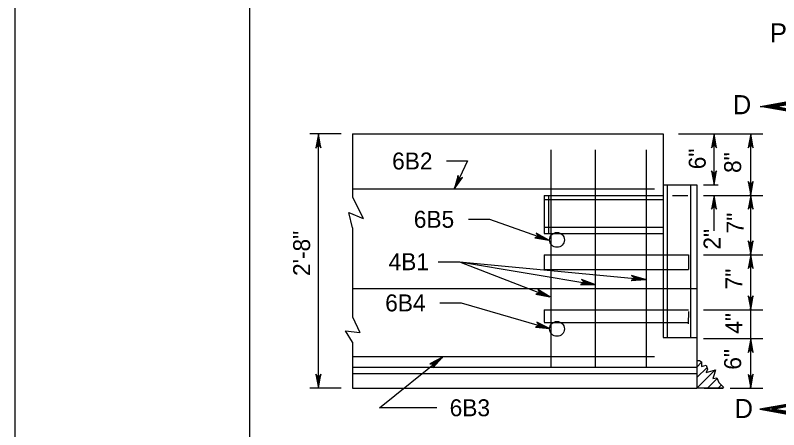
# Model space of a CAD drawing. Extents: x 499866 to 500993, y 499985 to 500645.
# Drawn here: x 499944.8 to 500124.8, y 500452.8 to 500550.5 of the extents above; entities that cross this region are included whole.
import ezdxf

# ---------------------------------------------------------------- set-up
doc = ezdxf.new("R2010")
doc.units = 0
for name, color, linetype in [('1', 7, 'Continuous'), ('24', 7, 'Continuous'), ('41', 7, 'Continuous'), ('5', 7, 'Continuous'), ('60', 7, 'Continuous')]:
    doc.layers.add(name, color=color, linetype=linetype)

msp = doc.modelspace()

# ---------------------------------------------------------------- linework, layer by layer
at = {"layer": '1'}
msp.add_line((500000, 500630), (500000, 500000), dxfattribs=at)
at = {"layer": '24'}
for points in [[(500109.52, 500522.52), (500108.95, 500519.24), (500109.52, 500520.03), (500110.09, 500519.26), (500109.52, 500522.52), (500109.53, 500522.3), (500108.99, 500519.34), (500109.53, 500520.09), (500110.05, 500519.39), (500109.54, 500522.18), (500109.52, 500522.07), (500109.07, 500519.53), (500109.53, 500520.1), (500109.98, 500519.52), (500109.52, 500522.02), (500109.54, 500521.92), (500109.14, 500519.7), (500109.52, 500520.13), (500109.92, 500519.69), (500109.54, 500521.6), (500109.54, 500521.41), (500109.22, 500519.86), (500109.51, 500520.16), (500109.84, 500519.84), (500109.52, 500521.38), (500109.51, 500521.21), (500109.31, 500520.04), (500109.54, 500520.26), (500109.76, 500520.02), (500109.52, 500521.05), (500109.51, 500520.88), (500109.37, 500520.18), (500109.53, 500520.29), (500109.71, 500520.1), (500109.52, 500520.8), (500109.42, 500520.34), (500109.54, 500520.4), (500109.67, 500520.2), (500109.54, 500520.68), (500109.47, 500520.38), (500109.56, 500520.51), (500109.62, 500520.36), (500109.53, 500520.51), (500109.51, 500520.43)], [(500118.16, 500522.52), (500117.58, 500519.24), (500118.16, 500520.03), (500118.73, 500519.26), (500118.16, 500522.52), (500118.17, 500522.3), (500117.62, 500519.34), (500118.17, 500520.09), (500118.69, 500519.39), (500118.18, 500522.18), (500118.16, 500522.07), (500117.71, 500519.53), (500118.17, 500520.1), (500118.61, 500519.52), (500118.16, 500522.02), (500118.18, 500521.92), (500117.78, 500519.7), (500118.16, 500520.13), (500118.56, 500519.69), (500118.18, 500521.6), (500118.18, 500521.41), (500117.86, 500519.86), (500118.15, 500520.16), (500118.48, 500519.84), (500118.16, 500521.38), (500118.15, 500521.21), (500117.95, 500520.04), (500118.18, 500520.26), (500118.4, 500520.02), (500118.16, 500521.05), (500118.14, 500520.88), (500118.01, 500520.18), (500118.17, 500520.29), (500118.34, 500520.1), (500118.16, 500520.8), (500118.05, 500520.34), (500118.18, 500520.4), (500118.3, 500520.2), (500118.18, 500520.68), (500118.1, 500520.38), (500118.2, 500520.51), (500118.26, 500520.36), (500118.17, 500520.51), (500118.15, 500520.43)], [(500109.52, 500510.53), (500110.1, 500513.8), (500109.52, 500513.02), (500108.95, 500513.78), (500109.52, 500510.53), (500109.52, 500510.74), (500110.06, 500513.71), (500109.52, 500512.96), (500109, 500513.65), (500109.51, 500510.86), (500109.52, 500510.97), (500109.98, 500513.51), (500109.52, 500512.94), (500109.07, 500513.53), (500109.52, 500511.02), (500109.51, 500511.13), (500109.91, 500513.35), (500109.52, 500512.92), (500109.12, 500513.36), (500109.51, 500511.45), (500109.51, 500511.63), (500109.83, 500513.19), (500109.53, 500512.88), (500109.21, 500513.21), (500109.52, 500511.66), (500109.53, 500511.84), (500109.73, 500513.01), (500109.51, 500512.78), (500109.28, 500513.03), (500109.52, 500512), (500109.54, 500512.16), (500109.67, 500512.87), (500109.52, 500512.75), (500109.34, 500512.94), (500109.52, 500512.25), (500109.63, 500512.71), (500109.51, 500512.64), (500109.38, 500512.84), (500109.51, 500512.36), (500109.58, 500512.67), (500109.48, 500512.54), (500109.42, 500512.68), (500109.52, 500512.54), (500109.53, 500512.62)], [(500118.16, 500508.03), (500118.74, 500511.3), (500118.16, 500510.52), (500117.59, 500511.29), (500118.16, 500508.03), (500118.15, 500508.25), (500118.7, 500511.21), (500118.15, 500510.46), (500117.64, 500511.15), (500118.14, 500508.36), (500118.16, 500508.47), (500118.61, 500511.01), (500118.15, 500510.44), (500117.71, 500511.03), (500118.16, 500508.52), (500118.14, 500508.63), (500118.54, 500510.85), (500118.16, 500510.42), (500117.76, 500510.86), (500118.14, 500508.95), (500118.14, 500509.13), (500118.46, 500510.69), (500118.17, 500510.38), (500117.84, 500510.71), (500118.16, 500509.17), (500118.17, 500509.34), (500118.37, 500510.51), (500118.14, 500510.28), (500117.92, 500510.53), (500118.16, 500509.5), (500118.18, 500509.67), (500118.31, 500510.37), (500118.15, 500510.25), (500117.98, 500510.44), (500118.16, 500509.75), (500118.27, 500510.21), (500118.14, 500510.14), (500118.02, 500510.34), (500118.14, 500509.87), (500118.22, 500510.17), (500118.12, 500510.04), (500118.06, 500510.19), (500118.15, 500510.04), (500118.17, 500510.12)], [(500109.52, 500508.03), (500108.95, 500504.75), (500109.52, 500505.54), (500110.09, 500504.77), (500109.52, 500508.03), (500109.53, 500507.81), (500108.99, 500504.85), (500109.53, 500505.6), (500110.05, 500504.9), (500109.54, 500507.69), (500109.52, 500507.59), (500109.07, 500505.05), (500109.53, 500505.62), (500109.98, 500505.03), (500109.52, 500507.54), (500109.54, 500507.43), (500109.14, 500505.21), (500109.52, 500505.64), (500109.92, 500505.2), (500109.54, 500507.11), (500109.54, 500506.93), (500109.22, 500505.37), (500109.51, 500505.67), (500109.84, 500505.35), (500109.52, 500506.89), (500109.51, 500506.72), (500109.31, 500505.55), (500109.54, 500505.77), (500109.76, 500505.53), (500109.52, 500506.56), (500109.51, 500506.39), (500109.37, 500505.69), (500109.53, 500505.81), (500109.71, 500505.61), (500109.52, 500506.31), (500109.42, 500505.85), (500109.54, 500505.92), (500109.67, 500505.71), (500109.54, 500506.19), (500109.47, 500505.89), (500109.56, 500506.02), (500109.62, 500505.87), (500109.53, 500506.02), (500109.51, 500505.94)], [(500118.16, 500508.03), (500117.58, 500504.75), (500118.16, 500505.54), (500118.73, 500504.77), (500118.16, 500508.03), (500118.17, 500507.81), (500117.62, 500504.85), (500118.17, 500505.6), (500118.69, 500504.9), (500118.18, 500507.69), (500118.16, 500507.59), (500117.71, 500505.05), (500118.17, 500505.62), (500118.61, 500505.03), (500118.16, 500507.54), (500118.18, 500507.43), (500117.78, 500505.21), (500118.16, 500505.64), (500118.56, 500505.2), (500118.18, 500507.11), (500118.18, 500506.93), (500117.86, 500505.37), (500118.15, 500505.67), (500118.48, 500505.35), (500118.16, 500506.89), (500118.15, 500506.72), (500117.95, 500505.55), (500118.18, 500505.77), (500118.4, 500505.53), (500118.16, 500506.56), (500118.14, 500506.39), (500118.01, 500505.69), (500118.17, 500505.81), (500118.34, 500505.61), (500118.16, 500506.31), (500118.05, 500505.85), (500118.18, 500505.92), (500118.3, 500505.71), (500118.18, 500506.19), (500118.1, 500505.89), (500118.2, 500506.02), (500118.26, 500505.87), (500118.17, 500506.02), (500118.15, 500505.94)], [(500118.16, 500494.04), (500118.74, 500497.31), (500118.16, 500496.53), (500117.59, 500497.3), (500118.16, 500494.04), (500118.15, 500494.26), (500118.7, 500497.22), (500118.15, 500496.47), (500117.64, 500497.16), (500118.14, 500494.37), (500118.16, 500494.48), (500118.61, 500497.02), (500118.15, 500496.45), (500117.71, 500497.04), (500118.16, 500494.53), (500118.14, 500494.64), (500118.54, 500496.86), (500118.16, 500496.43), (500117.76, 500496.87), (500118.14, 500494.96), (500118.14, 500495.14), (500118.46, 500496.7), (500118.17, 500496.4), (500117.84, 500496.72), (500118.16, 500495.18), (500118.17, 500495.35), (500118.37, 500496.52), (500118.14, 500496.29), (500117.92, 500496.54), (500118.16, 500495.51), (500118.18, 500495.68), (500118.31, 500496.38), (500118.15, 500496.26), (500117.98, 500496.45), (500118.16, 500495.76), (500118.27, 500496.22), (500118.14, 500496.15), (500118.02, 500496.35), (500118.14, 500495.88), (500118.22, 500496.18), (500118.12, 500496.05), (500118.06, 500496.2), (500118.15, 500496.05), (500118.17, 500496.13)], [(500118.16, 500494.04), (500117.58, 500490.77), (500118.16, 500491.55), (500118.73, 500490.78), (500118.16, 500494.04), (500118.17, 500493.82), (500117.62, 500490.86), (500118.17, 500491.61), (500118.69, 500490.91), (500118.18, 500493.7), (500118.16, 500493.6), (500117.71, 500491.06), (500118.17, 500491.63), (500118.61, 500491.04), (500118.16, 500493.55), (500118.18, 500493.44), (500117.78, 500491.22), (500118.16, 500491.65), (500118.56, 500491.21), (500118.18, 500493.12), (500118.18, 500492.94), (500117.86, 500491.38), (500118.15, 500491.68), (500118.48, 500491.36), (500118.16, 500492.9), (500118.15, 500492.73), (500117.95, 500491.56), (500118.18, 500491.78), (500118.4, 500491.54), (500118.16, 500492.57), (500118.14, 500492.4), (500118.01, 500491.7), (500118.17, 500491.82), (500118.34, 500491.63), (500118.16, 500492.32), (500118.05, 500491.86), (500118.18, 500491.93), (500118.3, 500491.73), (500118.18, 500492.2), (500118.1, 500491.9), (500118.2, 500492.03), (500118.26, 500491.88), (500118.17, 500492.03), (500118.15, 500491.95)], [(500118.16, 500481.05), (500118.74, 500484.32), (500118.16, 500483.54), (500117.59, 500484.31), (500118.16, 500481.05), (500118.15, 500481.27), (500118.7, 500484.23), (500118.15, 500483.48), (500117.64, 500484.17), (500118.14, 500481.38), (500118.16, 500481.49), (500118.61, 500484.03), (500118.15, 500483.46), (500117.71, 500484.05), (500118.16, 500481.54), (500118.14, 500481.65), (500118.54, 500483.87), (500118.16, 500483.44), (500117.76, 500483.88), (500118.14, 500481.97), (500118.14, 500482.15), (500118.46, 500483.71), (500118.17, 500483.41), (500117.84, 500483.73), (500118.16, 500482.19), (500118.17, 500482.36), (500118.37, 500483.53), (500118.14, 500483.3), (500117.92, 500483.55), (500118.16, 500482.52), (500118.18, 500482.69), (500118.31, 500483.39), (500118.15, 500483.27), (500117.98, 500483.46), (500118.16, 500482.77), (500118.27, 500483.23), (500118.14, 500483.16), (500118.02, 500483.36), (500118.14, 500482.89), (500118.22, 500483.19), (500118.12, 500483.06), (500118.06, 500483.21), (500118.15, 500483.06), (500118.17, 500483.14)], [(500118.16, 500474.27), (500117.58, 500471), (500118.16, 500471.78), (500118.73, 500471.01), (500118.16, 500474.27), (500118.17, 500474.05), (500117.62, 500471.09), (500118.17, 500471.84), (500118.69, 500471.15), (500118.18, 500473.94), (500118.16, 500473.83), (500117.71, 500471.29), (500118.17, 500471.86), (500118.61, 500471.27), (500118.16, 500473.78), (500118.18, 500473.67), (500117.78, 500471.45), (500118.16, 500471.88), (500118.56, 500471.44), (500118.18, 500473.35), (500118.18, 500473.17), (500117.86, 500471.61), (500118.15, 500471.91), (500118.48, 500471.59), (500118.16, 500473.13), (500118.15, 500472.96), (500117.95, 500471.79), (500118.18, 500472.02), (500118.4, 500471.77), (500118.16, 500472.8), (500118.14, 500472.63), (500118.01, 500471.93), (500118.17, 500472.05), (500118.34, 500471.86), (500118.16, 500472.55), (500118.05, 500472.09), (500118.18, 500472.16), (500118.3, 500471.96), (500118.18, 500472.43), (500118.1, 500472.13), (500118.2, 500472.26), (500118.26, 500472.11), (500118.17, 500472.26), (500118.15, 500472.18)], [(500118.16, 500462.56), (500118.74, 500465.84), (500118.16, 500465.06), (500117.59, 500465.82), (500118.16, 500462.56), (500118.15, 500462.78), (500118.7, 500465.75), (500118.15, 500464.99), (500117.64, 500465.69), (500118.14, 500462.9), (500118.16, 500463.01), (500118.61, 500465.55), (500118.15, 500464.98), (500117.71, 500465.56), (500118.16, 500463.06), (500118.14, 500463.17), (500118.54, 500465.39), (500118.16, 500464.95), (500117.76, 500465.4), (500118.14, 500463.48), (500118.14, 500463.67), (500118.46, 500465.22), (500118.17, 500464.92), (500117.84, 500465.24), (500118.16, 500463.7), (500118.17, 500463.87), (500118.37, 500465.04), (500118.14, 500464.82), (500117.92, 500465.06), (500118.16, 500464.04), (500118.18, 500464.2), (500118.31, 500464.9), (500118.15, 500464.79), (500117.98, 500464.98), (500118.16, 500464.29), (500118.27, 500464.74), (500118.14, 500464.68), (500118.02, 500464.88), (500118.14, 500464.4), (500118.22, 500464.7), (500118.12, 500464.58), (500118.06, 500464.72), (500118.15, 500464.58), (500118.17, 500464.65)]]:
    msp.add_lwpolyline(points, dxfattribs=at)
at = {"layer": '41'}
msp.add_lwpolyline([(499944.83, 500645), (500993, 500645), (500993, 499985), (499944.83, 499985)], close=True, dxfattribs=at)
at = {"layer": '5'}
for p, q in [((500021.65, 500522.52), (500014.28, 500522.52)), ((500016.28, 500462.56), (500016.28, 500522.52)), ((500024.28, 500522.52), (500097.5, 500522.52)), ((500024.28, 500522.52), (500024.28, 500507.65)), ((500097.5, 500522.52), (500097.5, 500510.53)), ((500101.14, 500522.52), (500120.99, 500522.52)), ((500109.52, 500510.53), (500109.52, 500522.52)), ((500118.16, 500508.03), (500118.16, 500522.52)), ((500071.02, 500518.73), (500071.02, 500467.56)), ((500081.51, 500518.73), (500081.51, 500467.56)), ((500093.5, 500518.73), (500093.5, 500467.56)), ((500046.45, 500516.13), (500051.45, 500516.13)), ((500051.45, 500516.13), (500048.28, 500509.5)), ((500097.5, 500510.53), (500105.49, 500510.53)), ((500097.5, 500510.53), (500097.5, 500474.55)), ((500098.5, 500510.53), (500098.5, 500474.55)), ((500104, 500510.53), (500104, 500474.55)), ((500105.49, 500510.53), (500105.49, 500462.56)), ((500107.01, 500510.53), (500110.49, 500510.53)), ((500024.28, 500509.53), (500095.5, 500509.53)), ((500069.52, 500508.03), (500097.5, 500508.03)), ((500069.52, 500508.03), (500069.52, 500499.04)), ((500070.52, 500508.03), (500070.52, 500499.04)), ((500099.7, 500508.03), (500103.35, 500508.03)), ((500107.01, 500508.03), (500120.99, 500508.03)), ((500109.52, 500499.63), (500109.52, 500508.03)), ((500118.16, 500494.04), (500118.16, 500508.03)), ((500024.28, 500507.65), (500026.86, 500502.55)), ((500069.52, 500507.03), (500097.5, 500507.03)), ((500024.28, 500500.36), (500023.47, 500503.95)), ((500023.47, 500503.95), (500026.86, 500502.55)), ((500051.64, 500502.38), (500056.64, 500502.38)), ((500056.64, 500502.38), (500070.58, 500497.48)), ((500024.28, 500500.36), (500024.28, 500479.4)), ((500069.52, 500500.53), (500097.5, 500500.53)), ((500069.52, 500499.04), (500097.5, 500499.04)), ((500069.52, 500494.04), (500103.5, 500494.04)), ((500069.52, 500494.04), (500069.52, 500490.54)), ((500103.5, 500494.04), (500103.5, 500490.54)), ((500107.01, 500494.04), (500120.99, 500494.04)), ((500118.16, 500481.05), (500118.16, 500494.04)), ((500044.53, 500492.39), (500049.53, 500492.39)), ((500049.53, 500492.39), (500093.34, 500488.22)), ((500049.53, 500492.39), (500081.45, 500487.04)), ((500049.53, 500492.39), (500070.86, 500484.1)), ((500069.52, 500490.54), (500103.5, 500490.54)), ((500024.28, 500486.05), (500105.49, 500486.05)), ((500044.91, 500482.68), (500049.91, 500482.68)), ((500049.91, 500482.68), (500070.77, 500476.62)), ((500069.52, 500481.05), (500069.49, 500478.1)), ((500069.52, 500481.05), (500103.5, 500481.05)), ((500107.01, 500481.05), (500120.99, 500481.05)), ((500118.16, 500474.27), (500118.16, 500481.05)), ((500024.28, 500479.4), (500026.07, 500475.7)), ((500103.49, 500480.68), (500103.46, 500477.73)), ((500069.52, 500478.05), (500103.5, 500478.05)), ((500024.28, 500473.41), (500022.67, 500476.1)), ((500022.67, 500476.1), (500026.07, 500475.7)), ((500097.5, 500474.55), (500105.49, 500474.55)), ((500107.01, 500474.27), (500120.99, 500474.27)), ((500118.16, 500462.56), (500118.16, 500474.27)), ((500024.28, 500473.41), (500024.28, 500462.56)), ((500024.28, 500470.06), (500095.5, 500470.06)), ((500030.68, 500457.95), (500045.49, 500469.9)), ((500105.49, 500467.56), (500106.6, 500468.67)), ((500024.28, 500467.56), (500105.49, 500467.56)), ((500105.49, 500465.06), (500107.88, 500467.45)), ((500105.49, 500462.56), (500109.79, 500466.86)), ((500024.28, 500466.06), (500105.49, 500466.06)), ((500107.99, 500462.56), (500110.28, 500464.85)), ((500110.49, 500462.56), (500111.26, 500463.33)), ((500021.65, 500462.56), (500014.28, 500462.56)), ((500024.28, 500462.56), (500105.49, 500462.56)), ((500107.2, 500462.56), (500111.6, 500462.56)), ((500113.32, 500462.56), (500120.99, 500462.56)), ((500044.21, 500457.95), (500030.68, 500457.95))]:
    msp.add_line(p, q, dxfattribs=at)
for points in [[(500120.43, 500528.99), (500130.41, 500530.76)], [(500130.35, 500527.26), (500120.43, 500528.99), (500121.1, 500528.98), (500130.13, 500530.63)], [(500129.95, 500527.4), (500121.45, 500528.94), (500121.79, 500528.99), (500129.52, 500530.37)], [(500129.57, 500527.62), (500121.94, 500528.99), (500122.27, 500528.94), (500129.03, 500530.16)], [(500129.06, 500527.78), (500123.23, 500528.94), (500123.79, 500528.94), (500128.53, 500529.91)], [(500128.6, 500528.03), (500123.89, 500528.99), (500124.43, 500529.02), (500127.99, 500529.63)], [(500016.28, 500522.52), (500015.7, 500519.19), (500016.28, 500519.99), (500016.86, 500519.21), (500016.28, 500522.52), (500016.29, 500522.3), (500015.74, 500519.29), (500016.29, 500520.05), (500016.82, 500519.35), (500016.3, 500522.18), (500016.28, 500522.07), (500015.82, 500519.49), (500016.29, 500520.07), (500016.74, 500519.47), (500016.28, 500522.02), (500016.3, 500521.91), (500015.89, 500519.65), (500016.28, 500520.09), (500016.69, 500519.64), (500016.3, 500521.59), (500016.3, 500521.4), (500015.98, 500519.82), (500016.27, 500520.13), (500016.6, 500519.8), (500016.28, 500521.36), (500016.27, 500521.19), (500016.07, 500520), (500016.3, 500520.23), (500016.53, 500519.98), (500016.28, 500521.02), (500016.27, 500520.86), (500016.13, 500520.14), (500016.29, 500520.26), (500016.47, 500520.07), (500016.28, 500520.77), (500016.17, 500520.3), (500016.3, 500520.37), (500016.43, 500520.17), (500016.3, 500520.65), (500016.22, 500520.35), (500016.32, 500520.48), (500016.38, 500520.33), (500016.29, 500520.48), (500016.27, 500520.4)], [(500048.28, 500509.5), (500050.24, 500512.24), (500049.37, 500511.78), (500049.18, 500512.73), (500048.28, 500509.5), (500048.37, 500509.7), (500050.16, 500512.18), (500049.34, 500511.73), (500049.17, 500512.59), (500048.41, 500509.81), (500048.47, 500509.9), (500050, 500512.03), (500049.33, 500511.71), (500049.18, 500512.44), (500048.5, 500509.95), (500048.53, 500510.06), (500049.87, 500511.91), (500049.33, 500511.69), (500049.15, 500512.27), (500048.67, 500510.35), (500048.75, 500510.51), (500049.72, 500511.8), (500049.32, 500511.65), (500049.16, 500512.09), (500048.78, 500510.54), (500048.86, 500510.69), (500049.56, 500511.68), (500049.25, 500511.57), (500049.15, 500511.89), (500048.92, 500510.85), (500049.01, 500510.99), (500049.44, 500511.57), (500049.25, 500511.54), (500049.17, 500511.79), (500049.03, 500511.07), (500049.33, 500511.45), (500049.19, 500511.44), (500049.16, 500511.68), (500049.07, 500511.19), (500049.27, 500511.43), (500049.12, 500511.36), (500049.13, 500511.52), (500049.15, 500511.34), (500049.2, 500511.41)], [(500070.58, 500497.48), (500067.64, 500499.14), (500068.19, 500498.32), (500067.27, 500498.03), (500070.58, 500497.48), (500070.37, 500497.55), (500067.71, 500499.07), (500068.25, 500498.29), (500067.41, 500498.03), (500070.25, 500497.58), (500070.15, 500497.63), (500067.87, 500498.92), (500068.26, 500498.29), (500067.55, 500498.06), (500070.11, 500497.65), (500070, 500497.67), (500068, 500498.8), (500068.29, 500498.29), (500067.73, 500498.05), (500069.69, 500497.78), (500069.52, 500497.84), (500068.13, 500498.67), (500068.33, 500498.28), (500067.9, 500498.08), (500069.49, 500497.86), (500069.33, 500497.93), (500068.27, 500498.52), (500068.41, 500498.23), (500068.1, 500498.09), (500069.17, 500497.98), (500069.02, 500498.05), (500068.39, 500498.41), (500068.45, 500498.22), (500068.2, 500498.12), (500068.93, 500498.06), (500068.53, 500498.32), (500068.55, 500498.18), (500068.31, 500498.13), (500068.81, 500498.09), (500068.55, 500498.26), (500068.64, 500498.12), (500068.48, 500498.11), (500068.65, 500498.15), (500068.58, 500498.19)], [(500081.45, 500487.04), (500078.27, 500488.17), (500078.96, 500487.46), (500078.09, 500487.02), (500081.45, 500487.04), (500081.23, 500487.07), (500078.35, 500488.11), (500079.02, 500487.44), (500078.23, 500487.04), (500081.11, 500487.08), (500081.01, 500487.11), (500078.54, 500487.99), (500079.03, 500487.44), (500078.37, 500487.09), (500080.96, 500487.12), (500080.84, 500487.13), (500078.69, 500487.9), (500079.06, 500487.44), (500078.55, 500487.12), (500080.53, 500487.18), (500080.34, 500487.21), (500078.84, 500487.79), (500079.09, 500487.44), (500078.71, 500487.17), (500080.31, 500487.23), (500080.14, 500487.27), (500079, 500487.67), (500079.19, 500487.4), (500078.91, 500487.22), (500079.98, 500487.29), (500079.81, 500487.33), (500079.13, 500487.58), (500079.22, 500487.41), (500079, 500487.26), (500079.73, 500487.33), (500079.29, 500487.52), (500079.33, 500487.38), (500079.11, 500487.29), (500079.61, 500487.33), (500079.32, 500487.46), (500079.43, 500487.34), (500079.27, 500487.3), (500079.43, 500487.37), (500079.36, 500487.4)], [(500093.34, 500488.22), (500090.09, 500489.12), (500090.82, 500488.46), (500089.99, 500487.96), (500093.34, 500488.22), (500093.12, 500488.23), (500090.18, 500489.07), (500090.88, 500488.44), (500090.13, 500487.99), (500093, 500488.23), (500092.89, 500488.26), (500090.37, 500488.96), (500090.9, 500488.44), (500090.27, 500488.05), (500092.84, 500488.27), (500092.73, 500488.26), (500090.52, 500488.88), (500090.92, 500488.45), (500090.44, 500488.09), (500092.41, 500488.29), (500092.22, 500488.31), (500090.68, 500488.78), (500090.96, 500488.45), (500090.6, 500488.16), (500092.19, 500488.33), (500092.02, 500488.35), (500090.85, 500488.67), (500091.06, 500488.42), (500090.79, 500488.21), (500091.85, 500488.36), (500091.69, 500488.39), (500090.99, 500488.6), (500091.09, 500488.42), (500090.88, 500488.27), (500091.6, 500488.38), (500091.15, 500488.54), (500091.2, 500488.4), (500090.99, 500488.3), (500091.48, 500488.38), (500091.19, 500488.48), (500091.3, 500488.37), (500091.15, 500488.32), (500091.31, 500488.4), (500091.23, 500488.43)], [(500070.86, 500484.1), (500067.97, 500485.85), (500068.5, 500485.01), (500067.56, 500484.76), (500070.86, 500484.1), (500070.65, 500484.17), (500068.04, 500485.77), (500068.55, 500484.98), (500067.71, 500484.75), (500070.53, 500484.21), (500070.44, 500484.26), (500068.2, 500485.62), (500068.57, 500484.98), (500067.85, 500484.77), (500070.39, 500484.28), (500070.28, 500484.3), (500068.33, 500485.5), (500068.59, 500484.98), (500068.03, 500484.76), (500069.98, 500484.42), (500069.8, 500484.49), (500068.45, 500485.36), (500068.63, 500484.97), (500068.2, 500484.78), (500069.78, 500484.52), (500069.62, 500484.59), (500068.59, 500485.21), (500068.71, 500484.91), (500068.4, 500484.79), (500069.46, 500484.64), (500069.31, 500484.72), (500068.7, 500485.1), (500068.75, 500484.91), (500068.5, 500484.81), (500069.23, 500484.73), (500068.83, 500485), (500068.85, 500484.86), (500068.61, 500484.81), (500069.11, 500484.76), (500068.85, 500484.94), (500068.94, 500484.8), (500068.78, 500484.8), (500068.95, 500484.83), (500068.88, 500484.87)], [(500070.77, 500476.62), (500067.74, 500478.12), (500068.34, 500477.33), (500067.43, 500476.99), (500070.77, 500476.62), (500070.56, 500476.68), (500067.82, 500478.05), (500068.4, 500477.31), (500067.57, 500477), (500070.44, 500476.7), (500070.34, 500476.75), (500067.99, 500477.91), (500068.42, 500477.3), (500067.72, 500477.03), (500070.29, 500476.76), (500070.18, 500476.78), (500068.13, 500477.8), (500068.44, 500477.3), (500067.9, 500477.04), (500069.87, 500476.87), (500069.69, 500476.92), (500068.26, 500477.67), (500068.48, 500477.3), (500068.07, 500477.08), (500069.66, 500476.95), (500069.49, 500477.01), (500068.41, 500477.53), (500068.57, 500477.25), (500068.27, 500477.1), (500069.34, 500477.04), (500069.18, 500477.1), (500068.53, 500477.43), (500068.6, 500477.25), (500068.36, 500477.13), (500069.09, 500477.11), (500068.68, 500477.35), (500068.7, 500477.21), (500068.47, 500477.14), (500068.97, 500477.13), (500068.7, 500477.29), (500068.8, 500477.15), (500068.64, 500477.14), (500068.81, 500477.19), (500068.74, 500477.23)], [(500045.49, 500469.9), (500042.54, 500468.27), (500043.52, 500468.31), (500043.28, 500467.37), (500045.49, 500469.9), (500045.32, 500469.75), (500042.64, 500468.29), (500043.57, 500468.34), (500043.36, 500467.49), (500045.24, 500469.67), (500045.14, 500469.61), (500042.85, 500468.35), (500043.59, 500468.35), (500043.41, 500467.63), (500045.1, 500469.58), (500045.03, 500469.5), (500043.02, 500468.4), (500043.6, 500468.37), (500043.51, 500467.78), (500044.78, 500469.3), (500044.63, 500469.18), (500043.2, 500468.44), (500043.62, 500468.4), (500043.57, 500467.94), (500044.59, 500469.17), (500044.45, 500469.07), (500043.4, 500468.48), (500043.72, 500468.45), (500043.67, 500468.11), (500044.33, 500468.96), (500044.19, 500468.87), (500043.55, 500468.53), (500043.74, 500468.47), (500043.7, 500468.21), (500044.13, 500468.8), (500043.7, 500468.59), (500043.83, 500468.54), (500043.75, 500468.31), (500044.05, 500468.71), (500043.76, 500468.58), (500043.93, 500468.58), (500043.85, 500468.44), (500043.91, 500468.61), (500043.84, 500468.57)], [(500105.5, 500469.09), (500106.13, 500469.09), (500106.6, 500468.78), (500106.6, 500467.68), (500107.7, 500467.99), (500108.01, 500467.05), (500107.7, 500466.26), (500109.9, 500466.89), (500109.59, 500465.79), (500109.27, 500464.85), (500110.21, 500465.01), (500110.68, 500463.91), (500111.78, 500462.81), (500111.6, 500462.56), (500105.51, 500462.54)], [(500016.28, 500462.56), (500016.87, 500465.89), (500016.28, 500465.09), (500015.7, 500465.87), (500016.28, 500462.56), (500016.28, 500462.78), (500016.83, 500465.79), (500016.28, 500465.03), (500015.75, 500465.74), (500016.27, 500462.9), (500016.28, 500463.01), (500016.74, 500465.59), (500016.28, 500465.01), (500015.82, 500465.61), (500016.28, 500463.06), (500016.27, 500463.18), (500016.67, 500465.43), (500016.28, 500464.99), (500015.88, 500465.44), (500016.27, 500463.5), (500016.27, 500463.68), (500016.59, 500465.26), (500016.29, 500464.95), (500015.96, 500465.29), (500016.28, 500463.72), (500016.29, 500463.89), (500016.5, 500465.08), (500016.27, 500464.85), (500016.04, 500465.1), (500016.28, 500464.06), (500016.3, 500464.23), (500016.44, 500464.94), (500016.28, 500464.82), (500016.1, 500465.01), (500016.28, 500464.31), (500016.39, 500464.78), (500016.27, 500464.71), (500016.14, 500464.91), (500016.27, 500464.43), (500016.34, 500464.73), (500016.24, 500464.61), (500016.18, 500464.75), (500016.28, 500464.61), (500016.29, 500464.68)], [(500130.25, 500459.34), (500120.33, 500457.61), (500121, 500457.62), (500130.03, 500455.97)], [(500129.85, 500459.2), (500121.35, 500457.65), (500121.69, 500457.61), (500129.42, 500456.23)], [(500120.33, 500457.61), (500130.3, 500455.84)], [(500129.47, 500458.98), (500121.84, 500457.61), (500122.17, 500457.65), (500128.93, 500456.43)], [(500128.96, 500458.82), (500123.13, 500457.66), (500123.69, 500457.66), (500128.43, 500456.69)], [(500128.5, 500458.57), (500123.79, 500457.61), (500124.33, 500457.57), (500127.89, 500456.97)]]:
    msp.add_lwpolyline(points, dxfattribs=at)
at = {"layer": '60'}
for centre in [(500072.52, 500497.54), (500072.52, 500476.55)]:
    msp.add_circle(centre, 1.75, dxfattribs=at)

# ---------------------------------------------------------------- texts
at = {"layer": '5'}
for s, height, p in [('PLAN', 4.5, (500122.7, 500544.07)), ('D', 4.5, (500113.95, 500527.16)), ('6B2', 4, (500033.65, 500514.13)), ('6B5', 4, (500038.76, 500500.38)), ('4B1', 4, (500032.82, 500490.39)), ('6B4', 4, (500032.02, 500480.68)), ('6B3', 4, (500047.21, 500455.95)), ('D', 4.5, (500114.36, 500455.53))]:
    msp.add_text(s, height=height, dxfattribs=at).set_placement(p)
for s, p in [('6"', (500107.56, 500514.18)), ('8"', (500115.91, 500513.31)), ('7"', (500116.48, 500499.07)), ('2\'-8"', (500014.32, 500489.02)), ('2"', (500111.05, 500495.24)), ('7"', (500116.2, 500485.87)), ('4"', (500116.2, 500475.41)), ('6"', (500115.91, 500466.93))]:
    msp.add_text(s, height=4, rotation=90, dxfattribs=at).set_placement(p)

doc.saveas('drawing.dxf')
